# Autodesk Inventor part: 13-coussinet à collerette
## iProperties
Created: 2011-02
Part Number: 13-coussinet à collerette
Document SubType Name: Modeling
Designer: eric
Density: 1 g/cm^3
Author: eric
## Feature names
1. Base1
